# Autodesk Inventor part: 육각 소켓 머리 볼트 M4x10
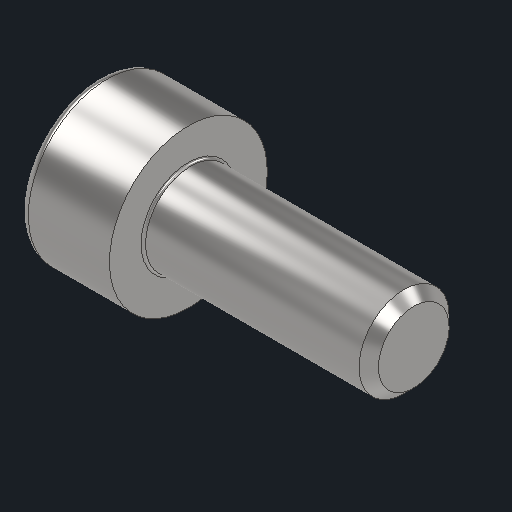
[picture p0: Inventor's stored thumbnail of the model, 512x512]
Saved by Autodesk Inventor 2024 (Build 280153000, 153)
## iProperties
Created: 2025-02
Part Number: 육각 소켓 머리 볼트 M4x10
Material: 강철, 연강
Description: 6각머리 태핑 나사
Document SubType Name: Modeling
Designer: kh_501
Density: 7.85 g/cm^3
Appearance: 기본값
Author: jhkim
Sending System: Autodesk Inventor 2025
Preprocessor: ST-DEVELOPER v20
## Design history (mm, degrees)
node "육각 소켓 머리 볼트 M4x101"
node "솔리드1"
body "Solid1"
